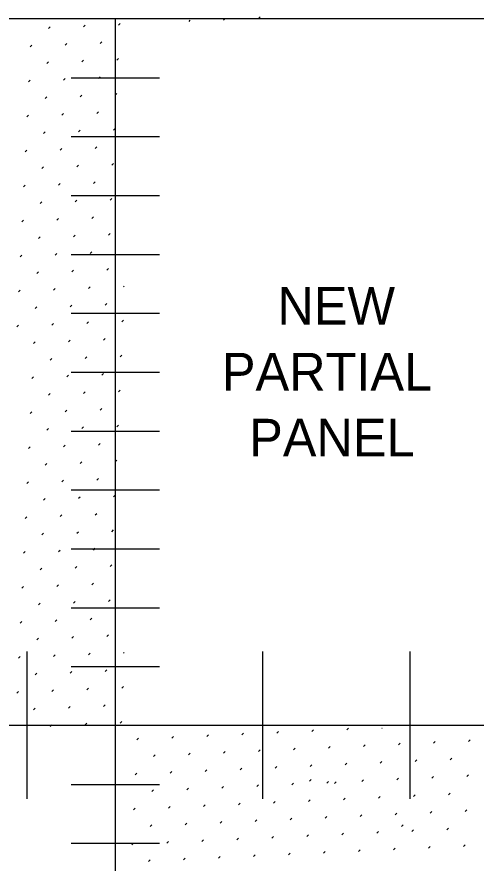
# Model space of a CAD drawing. Extents: x 49991.4 to 50021, y 49987.6 to 50011.4.
# Drawn here: x 50007.726 to 50008.7, y 49995.997 to 49997.793 of the extents above; entities that cross this region are included whole.
import ezdxf

# ---------------------------------------------------------------- set-up
doc = ezdxf.new("R2010")
doc.units = 0
for name, color, linetype in [('Level 1', 7, 'Continuous'), ('Level 10', 7, 'Continuous'), ('Level 2', 7, 'Continuous'), ('Level 4', 7, 'Continuous')]:
    doc.layers.add(name, color=color, linetype=linetype)

msp = doc.modelspace()

# ---------------------------------------------------------------- linework, layer by layer
at = {"layer": 'Level 1'}
for p, q in [((50006.0598, 49997.7903), (50007.9348, 49997.7903)), ((50007.9348, 49997.7903), (50007.9348, 49994.7903)), ((50007.9348, 49997.7903), (50008.8723, 49997.7903)), ((50002.3098, 49996.2901), (50007.9348, 49996.2901)), ((50007.9348, 49996.2901), (50008.8723, 49996.2901))]:
    msp.add_line(p, q, dxfattribs=at)
at = {"layer": 'Level 10'}
for p, q in [((50007.9419, 49997.7756), (50007.9455, 49997.7792)), ((50008.0916, 49997.7838), (50008.094, 49997.7863)), ((50008.1647, 49997.7863), (50008.1682, 49997.7898)), ((50008.239, 49997.7898), (50008.2425, 49997.7933)), ((50007.7934, 49997.7686), (50007.797, 49997.7721)), ((50007.8677, 49997.7721), (50007.8712, 49997.7756)), ((50007.7545, 49997.7297), (50007.7581, 49997.7332)), ((50007.8288, 49997.7332), (50007.8323, 49997.7367)), ((50007.903, 49997.7367), (50007.9066, 49997.7403)), ((50007.7899, 49997.6943), (50007.7934, 49997.6978)), ((50007.8641, 49997.6978), (50007.8677, 49997.7014)), ((50007.9384, 49997.7014), (50007.9419, 49997.7049)), ((50007.751, 49997.6554), (50007.7545, 49997.6589)), ((50007.8252, 49997.6589), (50007.8288, 49997.6625)), ((50007.8995, 49997.6625), (50007.903, 49997.666)), ((50007.7864, 49997.62), (50007.7899, 49997.6236)), ((50007.8606, 49997.6236), (50007.8641, 49997.6271)), ((50007.9349, 49997.6271), (50007.9384, 49997.6307)), ((50007.7475, 49997.5812), (50007.751, 49997.5847)), ((50007.8217, 49997.5847), (50007.8252, 49997.5882)), ((50007.896, 49997.5882), (50007.8995, 49997.5918)), ((50007.7828, 49997.5458), (50007.7863, 49997.5493)), ((50007.8571, 49997.5493), (50007.8606, 49997.5529)), ((50007.9313, 49997.5529), (50007.9349, 49997.5564)), ((50007.7439, 49997.5069), (50007.7474, 49997.5104)), ((50007.8182, 49997.5104), (50007.8217, 49997.514)), ((50007.8924, 49997.514), (50007.896, 49997.5175)), ((50007.7793, 49997.4715), (50007.7828, 49997.4751)), ((50007.8535, 49997.4751), (50007.8571, 49997.4786)), ((50007.9278, 49997.4786), (50007.9313, 49997.4822)), ((50007.7404, 49997.4326), (50007.7439, 49997.4362)), ((50007.8146, 49997.4362), (50007.8182, 49997.4397)), ((50007.8889, 49997.4397), (50007.8924, 49997.4433)), ((50007.7757, 49997.3973), (50007.7793, 49997.4008)), ((50007.85, 49997.4008), (50007.8535, 49997.4044)), ((50007.9242, 49997.4044), (50007.9278, 49997.4079)), ((50007.8111, 49997.3619), (50007.8146, 49997.3655)), ((50007.8853, 49997.3655), (50007.8889, 49997.369)), ((50007.7368, 49997.3584), (50007.7404, 49997.3619)), ((50007.8464, 49997.3266), (50007.85, 49997.3301)), ((50007.9207, 49997.3301), (50007.9242, 49997.3337)), ((50007.7722, 49997.323), (50007.7757, 49997.3266)), ((50007.8818, 49997.2912), (50007.8853, 49997.2948)), ((50007.7333, 49997.2841), (50007.7368, 49997.2877)), ((50007.8075, 49997.2877), (50007.8111, 49997.2912)), ((50007.9171, 49997.2559), (50007.9207, 49997.2594)), ((50007.7686, 49997.2488), (50007.7722, 49997.2523)), ((50007.8429, 49997.2523), (50007.8464, 49997.2559)), ((50007.8782, 49997.217), (50007.8818, 49997.2205)), ((50007.9525, 49997.2205), (50007.9538, 49997.2218)), ((50007.7297, 49997.2099), (50007.7333, 49997.2134)), ((50007.804, 49997.2134), (50007.8075, 49997.217)), ((50007.9136, 49997.1816), (50007.9171, 49997.1852)), ((50007.7651, 49997.1745), (50007.7686, 49997.1781)), ((50007.8393, 49997.1781), (50007.8429, 49997.1816)), ((50007.949, 49997.1463), (50007.9525, 49997.1498)), ((50007.7262, 49997.1356), (50007.7297, 49997.1392)), ((50007.8005, 49997.1392), (50007.804, 49997.1427)), ((50007.8747, 49997.1427), (50007.8782, 49997.1463)), ((50007.7616, 49997.1003), (50007.7651, 49997.1038)), ((50007.8358, 49997.1038), (50007.8393, 49997.1074)), ((50007.9101, 49997.1074), (50007.9136, 49997.1109)), ((50007.7969, 49997.0649), (50007.8004, 49997.0685)), ((50007.8712, 49997.0685), (50007.8747, 49997.072)), ((50007.9454, 49997.072), (50007.949, 49997.0755)), ((50007.758, 49997.026), (50007.7615, 49997.0296)), ((50007.8323, 49997.0296), (50007.8358, 49997.0331)), ((50007.9065, 49997.0331), (50007.9101, 49997.0366)), ((50007.7934, 49996.9907), (50007.7969, 49996.9942)), ((50007.8676, 49996.9942), (50007.8712, 49996.9977)), ((50007.9419, 49996.9978), (50007.9454, 49997.0013)), ((50007.7545, 49996.9518), (50007.758, 49996.9553)), ((50007.8287, 49996.9553), (50007.8323, 49996.9588)), ((50007.903, 49996.9589), (50007.9065, 49996.9624)), ((50007.7898, 49996.9164), (50007.7934, 49996.9199)), ((50007.8641, 49996.92), (50007.8676, 49996.9235)), ((50007.9383, 49996.9235), (50007.9419, 49996.927)), ((50007.7509, 49996.8775), (50007.7545, 49996.8811)), ((50007.8252, 49996.8811), (50007.8287, 49996.8846)), ((50007.8994, 49996.8846), (50007.903, 49996.8881)), ((50007.7863, 49996.8422), (50007.7898, 49996.8457)), ((50007.8605, 49996.8457), (50007.8641, 49996.8492)), ((50007.9348, 49996.8492), (50007.9383, 49996.8528)), ((50007.8216, 49996.8068), (50007.8252, 49996.8103)), ((50007.8959, 49996.8103), (50007.8994, 49996.8139)), ((50007.7474, 49996.8033), (50007.7509, 49996.8068)), ((50007.7827, 49996.7679), (50007.7863, 49996.7714)), ((50007.857, 49996.7715), (50007.8605, 49996.775)), ((50007.9312, 49996.775), (50007.9348, 49996.7785)), ((50007.8181, 49996.7326), (50007.8216, 49996.7361)), ((50007.8923, 49996.7361), (50007.8959, 49996.7396)), ((50007.7438, 49996.729), (50007.7474, 49996.7325)), ((50007.8534, 49996.6972), (50007.857, 49996.7007)), ((50007.9277, 49996.7007), (50007.9312, 49996.7043)), ((50007.7792, 49996.6937), (50007.7827, 49996.6972)), ((50007.8888, 49996.6618), (50007.8923, 49996.6654)), ((50007.7403, 49996.6548), (50007.7438, 49996.6583)), ((50007.8146, 49996.6583), (50007.8181, 49996.6618)), ((50007.9242, 49996.6265), (50007.9277, 49996.63)), ((50007.7757, 49996.6194), (50007.7792, 49996.6229)), ((50007.8499, 49996.6229), (50007.8534, 49996.6265)), ((50007.7368, 49996.5805), (50007.7403, 49996.584)), ((50007.811, 49996.584), (50007.8145, 49996.5876)), ((50007.8853, 49996.5876), (50007.8888, 49996.5911)), ((50007.9206, 49996.5522), (50007.9242, 49996.5558)), ((50007.7721, 49996.5451), (50007.7756, 49996.5487)), ((50007.8464, 49996.5487), (50007.8499, 49996.5522)), ((50007.7332, 49996.5062), (50007.7367, 49996.5098)), ((50007.8075, 49996.5098), (50007.811, 49996.5133)), ((50007.8817, 49996.5133), (50007.8853, 49996.5169)), ((50007.7686, 49996.4709), (50007.7721, 49996.4744)), ((50007.8428, 49996.4744), (50007.8464, 49996.478)), ((50007.9171, 49996.478), (50007.9206, 49996.4815)), ((50007.7297, 49996.432), (50007.7332, 49996.4355)), ((50007.8039, 49996.4355), (50007.8075, 49996.4391)), ((50007.8782, 49996.4391), (50007.8817, 49996.4426)), ((50007.9524, 49996.4426), (50007.9538, 49996.444)), ((50007.765, 49996.3966), (50007.7686, 49996.4002)), ((50007.8393, 49996.4002), (50007.8428, 49996.4037)), ((50007.9135, 49996.4037), (50007.9171, 49996.4073)), ((50007.7261, 49996.3577), (50007.7297, 49996.3613)), ((50007.8004, 49996.3613), (50007.8039, 49996.3648)), ((50007.8746, 49996.3648), (50007.8782, 49996.3684)), ((50007.9489, 49996.3684), (50007.9524, 49996.3719)), ((50007.7615, 49996.3224), (50007.765, 49996.3259)), ((50007.8357, 49996.3259), (50007.8393, 49996.3295)), ((50007.91, 49996.3295), (50007.9135, 49996.333)), ((50007.7968, 49996.287), (50007.8004, 49996.2906)), ((50007.8711, 49996.2906), (50007.8746, 49996.2941)), ((50007.9453, 49996.2941), (50007.9489, 49996.2977)), ((50008.1292, 49996.2658), (50008.1327, 49996.2694)), ((50008.2035, 49996.2694), (50008.207, 49996.2729)), ((50008.2777, 49996.2729), (50008.2812, 49996.2765)), ((50008.352, 49996.2765), (50008.3555, 49996.28)), ((50008.4262, 49996.28), (50008.4298, 49996.2836)), ((50008.5005, 49996.2836), (50008.5007, 49996.2838)), ((50007.9807, 49996.2588), (50007.9842, 49996.2623)), ((50008.055, 49996.2623), (50008.0585, 49996.2658)), ((50008.5358, 49996.2482), (50008.5394, 49996.2517)), ((50008.6101, 49996.2517), (50008.6136, 49996.2553)), ((50008.6843, 49996.2553), (50008.6879, 49996.2588)), ((50008.1646, 49996.2305), (50008.1681, 49996.234)), ((50008.2388, 49996.234), (50008.2424, 49996.2376)), ((50008.3131, 49996.2376), (50008.3166, 49996.2411)), ((50008.3873, 49996.2411), (50008.3909, 49996.2447)), ((50008.4616, 49996.2447), (50008.4651, 49996.2482)), ((50008.0161, 49996.2234), (50008.0196, 49996.2269)), ((50008.0903, 49996.2269), (50008.0938, 49996.2305)), ((50008.5712, 49996.2128), (50008.5747, 49996.2164)), ((50008.6454, 49996.2164), (50008.649, 49996.2199)), ((50008.1999, 49996.1951), (50008.2035, 49996.1987)), ((50008.2742, 49996.1987), (50008.2777, 49996.2022)), ((50008.3484, 49996.2022), (50008.352, 49996.2058)), ((50008.4227, 49996.2058), (50008.4262, 49996.2093)), ((50008.4969, 49996.2093), (50008.5005, 49996.2128)), ((50007.9772, 49996.1845), (50007.9807, 49996.188)), ((50008.0514, 49996.1881), (50008.0549, 49996.1916)), ((50008.1257, 49996.1916), (50008.1292, 49996.1951)), ((50008.6065, 49996.1775), (50008.6101, 49996.181)), ((50008.6808, 49996.181), (50008.6843, 49996.1846)), ((50008.2353, 49996.1598), (50008.2388, 49996.1633)), ((50008.3095, 49996.1633), (50008.3131, 49996.1669)), ((50008.3469, 49996.1711), (50008.3505, 49996.1746)), ((50008.3838, 49996.1669), (50008.3873, 49996.1704)), ((50008.4001, 49996.1659), (50008.4036, 49996.1694)), ((50008.458, 49996.1704), (50008.4616, 49996.1739)), ((50008.5323, 49996.174), (50008.5358, 49996.1775)), ((50008.0125, 49996.1492), (50008.016, 49996.1527)), ((50008.0868, 49996.1527), (50008.0903, 49996.1562)), ((50008.161, 49996.1562), (50008.1646, 49996.1598)), ((50008.6419, 49996.1421), (50008.6454, 49996.1457)), ((50008.2706, 49996.1244), (50008.2742, 49996.128)), ((50008.3449, 49996.128), (50008.3484, 49996.1315)), ((50008.4191, 49996.1315), (50008.4227, 49996.135)), ((50008.4934, 49996.1351), (50008.4969, 49996.1386)), ((50008.5676, 49996.1386), (50008.5712, 49996.1421)), ((50007.9736, 49996.1103), (50007.9772, 49996.1138)), ((50008.0479, 49996.1138), (50008.0514, 49996.1173)), ((50008.1221, 49996.1173), (50008.1257, 49996.1209)), ((50008.1964, 49996.1209), (50008.1999, 49996.1244)), ((50008.603, 49996.1032), (50008.6065, 49996.1068)), ((50008.6772, 49996.1068), (50008.6808, 49996.1103)), ((50008.2317, 49996.0855), (50008.2353, 49996.0891)), ((50008.306, 49996.0891), (50008.3095, 49996.0926)), ((50008.3802, 49996.0926), (50008.3838, 49996.0961)), ((50008.4545, 49996.0962), (50008.458, 49996.0997)), ((50008.5287, 49996.0997), (50008.5323, 49996.1032)), ((50008.009, 49996.0749), (50008.0125, 49996.0784)), ((50008.0832, 49996.0784), (50008.0868, 49996.082)), ((50008.1575, 49996.082), (50008.161, 49996.0855)), ((50008.5422, 49996.0747), (50008.5458, 49996.0782)), ((50008.6384, 49996.0679), (50008.6419, 49996.0714)), ((50008.2671, 49996.0502), (50008.2706, 49996.0537)), ((50008.3413, 49996.0537), (50008.3449, 49996.0573)), ((50008.4156, 49996.0573), (50008.4191, 49996.0608)), ((50008.4898, 49996.0608), (50008.4934, 49996.0643)), ((50008.5641, 49996.0643), (50008.5676, 49996.0679)), ((50007.9701, 49996.036), (50007.9736, 49996.0395)), ((50008.0443, 49996.0395), (50008.0479, 49996.0431)), ((50008.1186, 49996.0431), (50008.1221, 49996.0466)), ((50008.1928, 49996.0466), (50008.1964, 49996.0502)), ((50008.6737, 49996.0325), (50008.6772, 49996.0361)), ((50008.3024, 49996.0148), (50008.306, 49996.0184)), ((50008.3767, 49996.0184), (50008.3802, 49996.0219)), ((50008.4509, 49996.0219), (50008.4545, 49996.0254)), ((50008.5252, 49996.0254), (50008.5287, 49996.029)), ((50008.5995, 49996.029), (50008.603, 49996.0325)), ((50008.0054, 49996.0006), (50008.009, 49996.0042)), ((50008.0797, 49996.0042), (50008.0832, 49996.0077)), ((50008.1539, 49996.0077), (50008.1575, 49996.0113)), ((50008.2282, 49996.0113), (50008.2317, 49996.0148))]:
    msp.add_line(p, q, dxfattribs=at)
at = {"layer": 'Level 4'}
for p, q in [((50007.841, 49997.6642), (50008.0285, 49997.6642)), ((50007.841, 49997.5392), (50008.0285, 49997.5392)), ((50007.841, 49997.4142), (50008.0285, 49997.4142)), ((50007.841, 49997.2892), (50008.0285, 49997.2892)), ((50007.841, 49997.1642), (50008.0285, 49997.1642)), ((50007.841, 49997.0392), (50008.0285, 49997.0392)), ((50007.841, 49996.9142), (50008.0285, 49996.9142)), ((50007.841, 49996.7892), (50008.0285, 49996.7892)), ((50007.841, 49996.6642), (50008.0285, 49996.6642)), ((50007.841, 49996.5392), (50008.0285, 49996.5392)), ((50007.7473, 49996.4463), (50007.7473, 49996.1338)), ((50008.2473, 49996.4463), (50008.2473, 49996.1338)), ((50008.5598, 49996.4463), (50008.5598, 49996.1338)), ((50007.841, 49996.4142), (50008.0285, 49996.4142)), ((50007.841, 49996.1642), (50008.0285, 49996.1642)), ((50007.841, 49996.0392), (50008.0285, 49996.0392))]:
    msp.add_line(p, q, dxfattribs=at)

# ---------------------------------------------------------------- texts
at = {"layer": 'Level 2'}
for s, p in [('NEW', (50008.2788, 49997.1403)), ('PARTIAL ', (50008.1611, 49997.0003)), ('PANEL', (50008.219, 49996.8603))]:
    msp.add_text(s, height=0.08, dxfattribs=at).set_placement(p)

doc.saveas('drawing.dxf')
